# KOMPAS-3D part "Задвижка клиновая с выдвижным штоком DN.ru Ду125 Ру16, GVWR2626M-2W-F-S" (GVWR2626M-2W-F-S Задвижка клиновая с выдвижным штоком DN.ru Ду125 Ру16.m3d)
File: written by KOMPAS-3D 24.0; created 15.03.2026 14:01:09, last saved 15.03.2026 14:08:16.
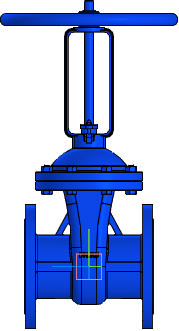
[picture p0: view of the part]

Document properties: Автор: R2D2; Полное имя файла: GVWR2626M-2W-F-S Задвижка клиновая с выдвижным штоком DN.ru Ду125 Ру16.cdw

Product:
- Part/product: Задвижка клиновая с выдвижным штоком DN.ru Ду125 Ру16  | designation GVWR2626M-2W-F-S
    Масса: 40
    Раздел спецификации: Прочие изделия
    Форматы листов документа: A2
    Примечание: D040-10503

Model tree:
1. Операция без истории:1

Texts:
  GVWR2626M-2W-F-S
